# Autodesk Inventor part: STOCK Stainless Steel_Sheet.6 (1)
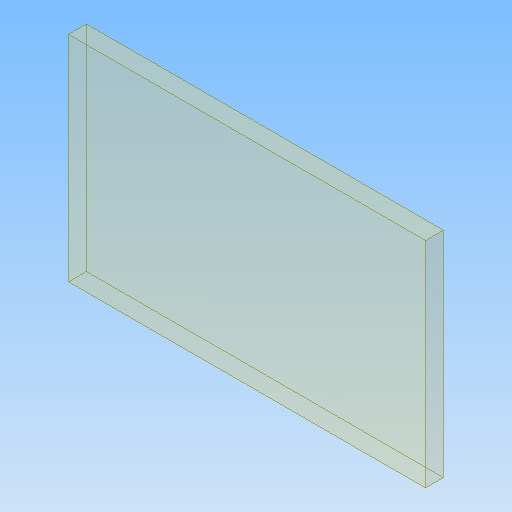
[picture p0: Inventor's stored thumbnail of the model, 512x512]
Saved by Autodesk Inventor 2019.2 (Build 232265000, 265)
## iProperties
Created: 2019-02
Part Number: STOCK Stainless Steel_Sheet.6 (1)
Material: Stainless Steel
Document SubType Name: Modeling
Designer: User
Density: 8 g/cm^3
Appearance: Semi-Polished
Author: User
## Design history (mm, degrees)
sketch "STOCK Stainless Steel sketch"
  geometry: L1 (0, 0)-(0, 76.2); L2 (0, 76.2)-(127, 76.2); L3 (127, 76.2)-(127, 0); L4 (127, 0)-(0, 0)
  constraints: 8 end point
extrude "STOCK Stainless Steel extrude" new body sketch "STOCK Stainless Steel sketch" stored distance "d0" = 6.34; taper "d1" = 0 deg
node "STOCK Stainless Steel"
